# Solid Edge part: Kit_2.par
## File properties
Sűrűség: 0,000 kg/m^3
Pontosság: 0,990
Author: ahadarics
Last saved by: psaghy
Revision: 77
Username: ahadarics
Dokumentum tartalom típus: 0
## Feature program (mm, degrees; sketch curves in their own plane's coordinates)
base feature "unnamed BaseFeature 1"
sketch for "Furat_1" plane through (0, 0, -205) normal (0, 0, -1) x-axis (1, 0, 0)
  hole centre (-135, 135) bore radius 10.376
hole "Furat_1" nominal diameter 24 finite  ThreadDepth = 28 mm
sketch for "unnamed Hole 1" plane through (0, 0, -205) normal (0, 0, -1) x-axis (1, 0, 0)
  hole centre (-135, -135) bore radius 10.376
hole "unnamed Hole 1" finite
sketch for "unnamed Hole 2" plane through (0, 0, -205) normal (0, 0, -1) x-axis (1, 0, 0)
  hole centre (135, -135) bore radius 10.376
hole "unnamed Hole 2" finite
sketch for "unnamed Hole 3" plane through (0, 0, -205) normal (0, 0, -1) x-axis (1, 0, 0)
  hole centre (135, 135) bore radius 10.376
hole "unnamed Hole 3" finite
pattern "unnamed Pattern 1" of "Furat_1", "unnamed Hole 1", "unnamed Hole 2", "unnamed Hole 3"
sketch for "Furat_5" plane through (35, -174, -175) normal (0, -1, 0) x-axis (0, 0, -1)
hole "Furat_5" diameter 33.249 finite  ThreadDepth = 21 mm
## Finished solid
Body 1: solid body, 573 faces, 1264 edges, 719 vertices, 2 internal voids.
  Faces by surface: cylinder 187, plane 126, torus 100, spline 98, cone 37, sphere 24, spun 1
  Edges by curve: curve on surface 460, line 383, circle 380, spline 19, intersection 17, ellipse 5
Bounding box of the edges (mm; curved faces can reach further): 350.000 x 350.000 x 75.000, from (-175, -175, -215) to (175, 175, -140).
Cylindrical faces by radius (mm): R1.5 x5, R2 x3, R3 x21, R3.004 x2, R3.0417 x1, R4 x1, R5 x42, R5.5 x1, R5.6 x1, R8 x1, R10 x45, R10.0007 x12, R10.37 x4, R10.376 x4, R12 x1, R12.25 x4, R12.5 x1, R15.14 x1, R15.1455 x1, R16 x1, R18 x4, R18.5 x4, R20 x1, R22 x2, R24 x1, R32.5 x8, R40 x4, R40.5 x2, R55 x1, R60 x8
Conical faces (half-angle, radius in mm at the cone's reference point): 0.2057 deg R3.0535 x1, 0.2256 deg R3.0398 x1, 45 deg R5.35 x1, 45 deg R5.75 x1, 45 deg R7.9 x1, 45 deg R10.37 x8, 45 deg R11.376 x4, 45 deg R12.75 x4, 45 deg R15.14 x1, 45 deg R19.5 x4, 45 deg R38.5 x4, 45 deg R143.5 x6, 59 deg R6.25 x1
Toroidal faces (ring radius, tube radius in mm): R3 r2 x2, R5 r5 x1, R6.8992 r2.0029 x1, R8.012 r3.0039 x1, R8.0233 r3.0048 x8, R8.0234 r3.0048 x4, R8.0627 r3.0049 x8, R11.5 r1.5 x8, R15 r10 x1, R17 r1 x12, R19 r5 x1, R21 r5 x1, R29 r5 x1, R31 r1.5 x4, R37 r3 x4, R37.5 r5 x4, R42.5 r10 x8, R53.5 r1.5 x1, R56.5 r1.5 x1, R58.5 r1.5 x1, R62 r2 x1, R65 r5 x9, R70 r10 x6, R138.9289 r5 x6, R148.0711 r5 x6
Spherical faces by radius (mm): R5 x4, R5.0686 x12, R10 x8
Planar faces by outward normal: +x 14, +y 9, +z 2, -x 12, -y 15, -z 56, oblique 18
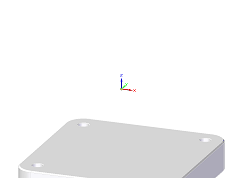
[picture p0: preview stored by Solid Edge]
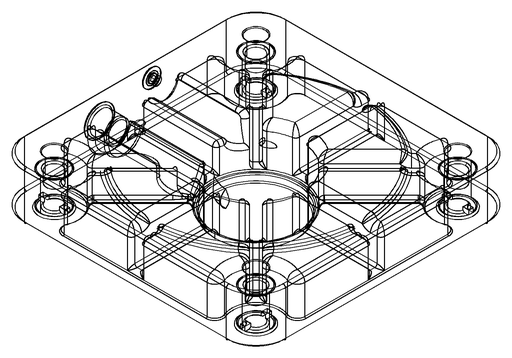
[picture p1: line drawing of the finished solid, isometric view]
